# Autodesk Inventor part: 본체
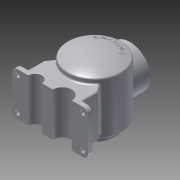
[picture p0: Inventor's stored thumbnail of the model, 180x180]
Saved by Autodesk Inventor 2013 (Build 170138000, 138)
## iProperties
Created: 2018-08
Part Number: 본체
Material: 알루미늄 6061
Document SubType Name: Modeling
Designer: Administrator
Density: 2.71 g/cm^3
Mass: 1886.75 g
Surface Area: 1089.75 cm^2
Volume: 696.217 cm^3
Author: Administrator
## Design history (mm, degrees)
sketch "스케치2"
  geometry: L1 (70, 40)-(-70, 40); L2 (-70, 40)-(-70, -40); L3 (-70, -40)-(70, -40); L4 (70, -40)-(70, 40); L5 (70, 40)-(-70, -40); L6 (-70, 40)-(70, -40); 1 further point
  constraints: 12 end point, 2 midpoint, 2 parallel, 1 horizontal, 1 perpendicular
  dimensions: "d2" = 80 distance between parallel lines of L3 L1; "d4" = 140 distance between parallel lines of L2 L4
extrude "돌출1" new body sketch "스케치2" distance "d5" = 10; taper "d6" = 0 deg
sketch "스케치4"
  geometry: L1 (82, -51.553)-(82, 121.07); L2 (82, -60)-(120, -60); L3 (120, -60)-(120, -48); L4 (120, -48)-(132, -48); L5 (132, -48)-(132, 48.671); L6 (0, -40)-(10, -40) reference; L7 (82, 60)-(82, -60); L8 (109, -60)-(109, -38); L9 (109, -38)-(119, -38); L10 (122, -35)-(122, 40.125); L11 (109, -60)-(120, -60); L12 (82, 60)-(82, 50); A1 r 116 centre (82, -56) between (132, 48.671) and (82, 60); A2 r 106 centre (82, -56) between (120.078, 42.925) and (82, 50); A3 r 3 centre (119, 40.125) between (122, 40.125) and (120.078, 42.925); A4 r 3 centre (119, -35) between (119, -38) and (122, -35); 3 further points
  constraints: 22 end point, 9 point on circle, 7 point on line, 4 centre point, 4 perpendicular, 4 tangent, 3 collinear, 3 parallel, 1 equal radius, 1 vertical
  dimensions: "d22" = 82 distance from line of point (0, 0) L1; "d23" = 50 distance between parallel lines of L5 L1; "d24" = 38 distance between parallel lines of L1 L3; "d27" = 12 distance between parallel lines of L4 L2; "d28" = 8 distance between parallel lines of L4 L6; "d29" = 116 radius of A1; "d30" = 10 radial gap between concentric circles of A1 A2; "d31" = 40 distance between parallel lines of L10 L7; "d32" = 27 distance between parallel lines of L8 L1; "d33" = 22 distance between parallel lines of L9 L2; "d89" = 3 radius of A3; "d104" = 108 vertical distance of L7.start L4.end
revolve "회전1" sketch "스케치4" stored, may be unused: angle "d34" = 90 deg
sketch "스케치3"
  geometry: L1 (70, 10)-(-70, 10) reference; L2 (70, 0)-(70, 10) reference; L3 (50, 38.563)-(50, 10); L4 (-50, 10)-(-50, 38.563); L5 (-70, 0)-(-70, 10) reference; L6 (-70, 10)-(-70, 80.948); L7 (70, 10)-(70, 68.048); L8 (-70, 10)-(-10.973, 94.3); L9 (70, 10)-(9.248, 96.763); L10 (-50, 38.563)-(-38.767, 54.606); L11 (50, 38.563)-(38.767, 54.606); L12 (-38.767, 54.606)-(-10.767, 35); L13 (-10.767, 35)-(10.767, 35); L14 (10.767, 35)-(38.767, 54.606); 1 further point
  constraints: 22 end point, 6 point on line, 4 perpendicular, 3 collinear, 2 parallel, 1 equal length
  dimensions: "d14" = 20 distance between parallel lines of L5 L4; "d15" = 20 distance between parallel lines of L2 L3; "d19" = 35 deg angle of L8 L6; "d20" = 35 deg angle of L7 L9; "d35" = 35 distance from line of L13 point (0, 0); "d36" = 28 horizontal distance of L10.end L12.end
extrude "돌출2" join sketch "스케치3" stored distance "d37" = 80; taper "d38" = 0 deg
fillet "모깎기1" dims "d39" = 10
sketch "스케치5"
  geometry: L1 (50, 40)-(50, -40) reference; L2 (50, -40)-(60, -40) reference; L3 (70, -30)-(70, 30) reference; L4 (60, 40)-(50, 40) reference; C1 r 4 at (60, 30); C2 r 4 at (60, -30); C3 r 4 at (-60, 30); C4 r 4 at (-60, -30); A1 r 10 centre (60, 30) between (70, 30) and (60, 40) reference; A2 r 10 centre (60, -30) between (60, -40) and (70, -30) reference; A3 r 10 centre (-60, 30) between (-60, 40) and (-70, 30) reference; A4 r 10 centre (-60, -30) between (-70, -30) and (-60, -40) reference; 1 further point
  constraints: 4 centre point, 4 coincident
  dimensions: "d40" = 8 diameter of C1; "d42" = 8 diameter of C2; "d43" = 8 diameter of C3; "d44" = 8 diameter of C4
extrude "돌출3" cut sketch "스케치5" distance "d45" = 10; taper "d46" = 0 deg
sketch "스케치6"
  geometry: L1 (-60, -82)-(60, -82) reference; C1 r 12.5 at (-27.5, -82); C2 r 17.5 at (22.5, -82); 1 further point
  constraints: 2 centre point, 2 point on line
  dimensions: "d50" = 27.5 distance of point (0, -82) C1.centre; "d51" = 22.5 distance of C2.centre point (0, -82); "d52" = 12.5 radius of C1; "d53" = 35 diameter of C2
extrude "돌출4" cut sketch "스케치6" distance "d54" = 90; taper "d55" = 0 deg
node "작업 평면1"
sketch "스케치7"
  geometry: L1 (-38, -60)-(38, -60) reference; L2 (0, 0)-(0, 80.618); C1 r 38 at (0, 2)
  constraints: 2 end point, 1 centre point, 1 perpendicular, 1 point on line
  dimensions: "d57" = 62 distance from line of L1 C1.centre; "d58" = 76 diameter of C1
extrude "돌출5" join sketch "스케치7" stored distance "d59" = 90; taper "d60" = 0 deg
sketch "스케치8"
  geometry: C1 r 38 at (0, 0) reference; C2 r 27 at (0, 0); 1 further point
  constraints: 1 centre point, 1 concentric
  dimensions: "d61" = 54 diameter of C2
extrude "돌출6" cut sketch "스케치8" stored distance "d63" = 90; taper "d64" = 0 deg
sketch "스케치9" dims "d65" = 65
  geometry: L1 (0, 2)-(0, 69.763); C1 r 38 at (0, 0) reference; 2 further points
  constraints: 2 end point, 1 point on line, 1 vertical, 1 vertical alignment, 3 other
hole "구멍1" sketch "스케치9" at (0, 32.5) diameter "d67" = 3.242; stored, may be unused: countersink angle "d71" = 90 deg, drill point angle "d73" = 118 deg; dims "d68" = 8, "d69" = 4, "d70" = 2, "d72" = 10
sketch "스케치10" dims "d77" = 65
  geometry: L1 (0, -82)-(0, 53.947); C1 r 38 at (0, 0) reference; 2 further points
  constraints: 2 end point, 1 point on line, 1 vertical, 1 vertical alignment, 3 other
hole "구멍2" sketch "스케치10" at (0, 32.5) diameter "d79" = 3.242; stored, may be unused: countersink angle "d83" = 90 deg, drill point angle "d85" = 118 deg; dims "d80" = 8, "d81" = 4, "d82" = 2, "d84" = 10
fillet "모깎기2" dims "d90" = 3
fillet "모깎기3" dims "d91" = 3
fillet "모깎기4" dims "d92" = 3
fillet "모깎기5" dims "d93" = 3
node "작업 평면2"
sketch "스케치11" dims "d95" = 65
  geometry: C1 r 50 at (60, 82) reference; A1 r 32.5 centre (60, 82) between (92.5, 82) and (27.5, 82); 2 further points
  constraints: 2 point on circle, 1 centre point, 1 coincident, 1 horizontal alignment, 5 other
feature "엠보싱1" sketch "스케치11" dims "d2" = 80, "d4" = 140, "d22" = 82, "d97" = 0.5, "d98" = 0
fillet "모깎기6" dims "d99" = 3
chamfer "모따기1" distance "d100" = 1; stored, may be unused: second distance "d101" = 2, angle "d102" = 45 deg
fillet "모깎기7" dims "d105" = 3
node "솔리드1"
pattern_circular "원형 패턴1" dims angle "d75" = 360 deg
pattern_circular "원형 패턴2" dims angle "d87" = 360 deg
node "투영된 루프1"
other parameters: "d56" = 147, "d94" = 18
